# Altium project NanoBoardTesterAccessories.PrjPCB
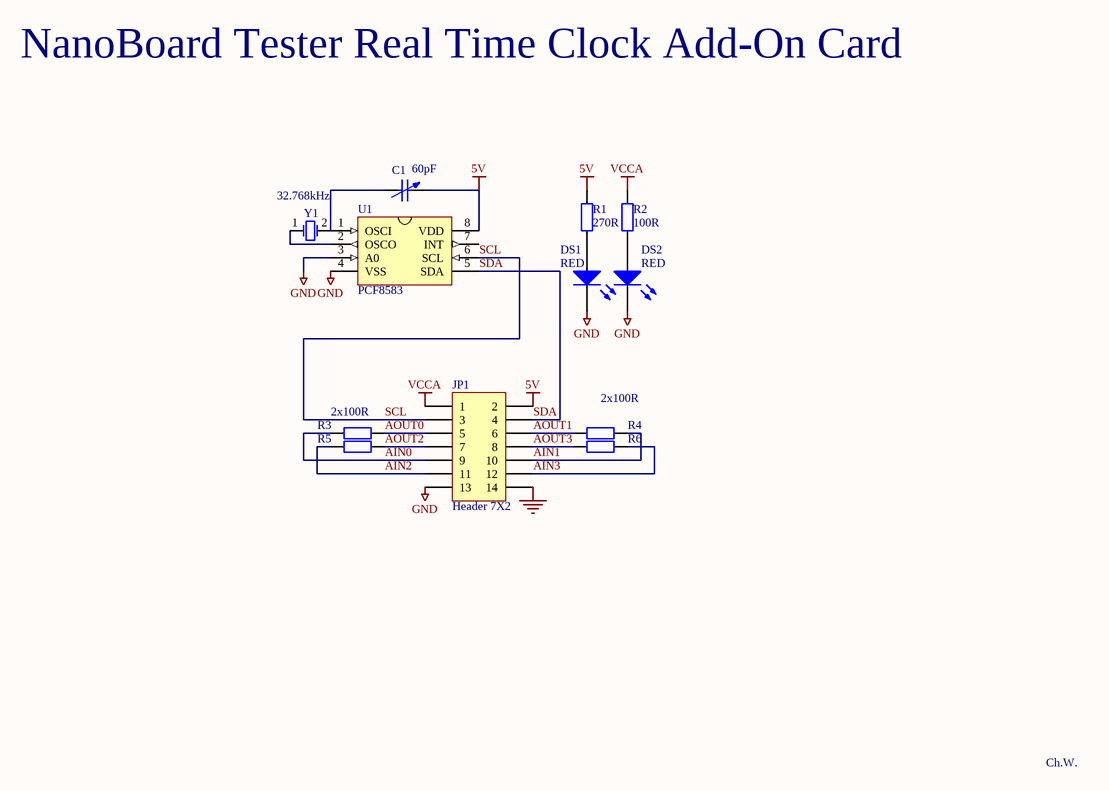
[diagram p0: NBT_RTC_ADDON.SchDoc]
3 sheets, 15 parts. Net scope: global (net labels, ports and power ports of the same name join across sheets).
Sheets:
  NBT_RTC_ADDON.SchDoc
  NBT_RS232_TESTPLUG.SchDoc
  NBT_JTAG_LOOP_CABLE.SCHDOC

## Sheet NBT_RTC_ADDON.SchDoc
size A4; Organization: Altium Limited; Address1: L3, 12a Rodborough Rd; Address2: Frenchs Forest; Address3: NSW; Address4: Australia 2086; DocumentNumber: 1; SheetNumber: 1; SheetTotal: 3

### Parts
C1  value 60pF  [C3225-1210]  (hidden comment: Cap Var)
DS1  LED2  [DSO-F2/D6.1]  (value not drawn)
DS2  LED2  [DSO-F2/D6.1]  (value not drawn)
JP1  Header 7X2  [HDR2X7]
R1  270R  [AXIAL-0.4]
R2  value 100R  [AXIAL-0.4]  (hidden comment: Generic Components)
R3  Res2  [AXIAL-0.4]  (value not drawn)
R4  Res2  [AXIAL-0.4]  (value not drawn)
R5  Res2  [AXIAL-0.4]  (value not drawn)
R6  Res2  [AXIAL-0.4]  (value not drawn)
U1  PCF8583  [DIP-8]
Y1  32.768kHz  [BCY-W2/D3.1]

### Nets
5V: C1.2 JP1.2 R1.2 U1.8(VDD)
GND: DS1.2(K) DS2.2(K) JP1.13 JP1.14 U1.3(A0) U1.4(VSS)
VCCA: JP1.1 R2.2
AIN0: JP1.9 R3.2
AIN1: JP1.10 R4.1
AIN2: JP1.11 R5.2
AIN3: JP1.12 R6.1
AOUT0: JP1.5 R3.1
AOUT1: JP1.6 R4.2
AOUT2: JP1.7 R5.1
AOUT3: JP1.8 R6.2
SCL: JP1.3 U1.6(SCL)
SDA: JP1.4 U1.5(SDA)
NetC1_1: C1.1 U1.1(OSCI) Y1.2(OSC2)
NetDS1_1: DS1.1(A) R1.1
NetDS2_1: DS2.1(A) R2.1
NetU1_2: U1.2(OSCO) Y1.1(OSC1)

Not connected (* = marked no-connect by the designer): U1 7(INT)

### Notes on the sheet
- NanoBoard Tester Real Time Clock Add-On Card
- (near R3) 2x100R
- 2x100R
- Ch.W.

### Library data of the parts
C1 = Cap Var: Variable or Adjustable Capacitor; Manufacturer: Generic Components; Class I: Passive
DS1 DS2 = LED2: Typical RED, GREEN, YELLOW, AMBER GaAs LED; Manufacturer: Generic Components; Class I: Optoelectronic
JP1 = Header 7X2: Header, 7-Pin, Dual row; Manufacturer: Generic Components; Class I: Connector
R1 = Res2: Resistor; Manufacturer: Generic Components; Class I: Passive
R2 = Res2: Resistor; Class I: Passive
R3-R6 = Res2: Resistor; Manufacturer: Generic Components; Class I: Passive; Value: 100R
U1 = PCF8583: Clock/Calendar with 240 x 8-bit RAM
Y1 = XTAL: Crystal Oscillator; Manufacturer: Generic Components

## Sheet NBT_RS232_TESTPLUG.SchDoc
size A4; Organization: Altium Limited; Address1: L3, 12a Rodborough Rd; Address2: Frenchs Forest; Address3: NSW; Address4: Australia 2086; DocumentNumber: 2; SheetNumber: 2; SheetTotal: 3
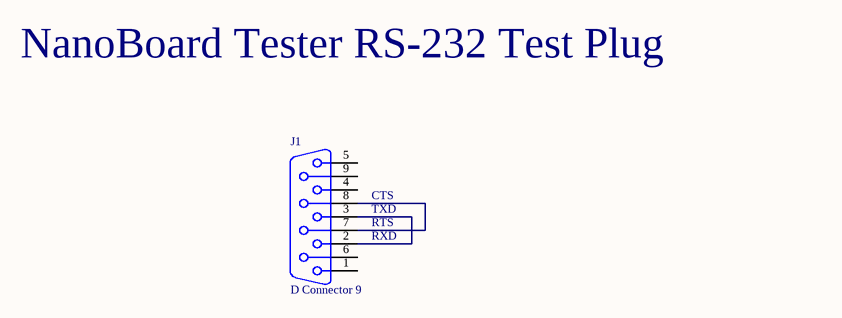
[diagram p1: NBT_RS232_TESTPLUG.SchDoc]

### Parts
J1  D Connector 9  [DSUB1.385-2H9]

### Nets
NetJ1_2: J1.2 J1.3
NetJ1_7: J1.7 J1.8

Not connected (* = marked no-connect by the designer): J1 1 4 5 6 9 10(MH1) 11(MH2)

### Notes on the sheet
- NanoBoard Tester RS-232 Test Plug
- (near J1) TXD
- (near J1) CTS
- (near J1) RXD
- (near J1) RTS

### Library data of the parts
J1 = D Connector 9: Receptacle Assembly, 9 Position, Right Angle; Manufacturer: Generic Components; Package Information: Latest Revision: O; Positions: 9

## Sheet NBT_JTAG_LOOP_CABLE.SCHDOC
size A4; Organization: Altium Limited; Address1: L3, 12a Rodborough Rd; Address2: Frenchs Forest; Address3: NSW; Address4: Australia 2086; DocumentNumber: 3; SheetNumber: 3; SheetTotal: 3
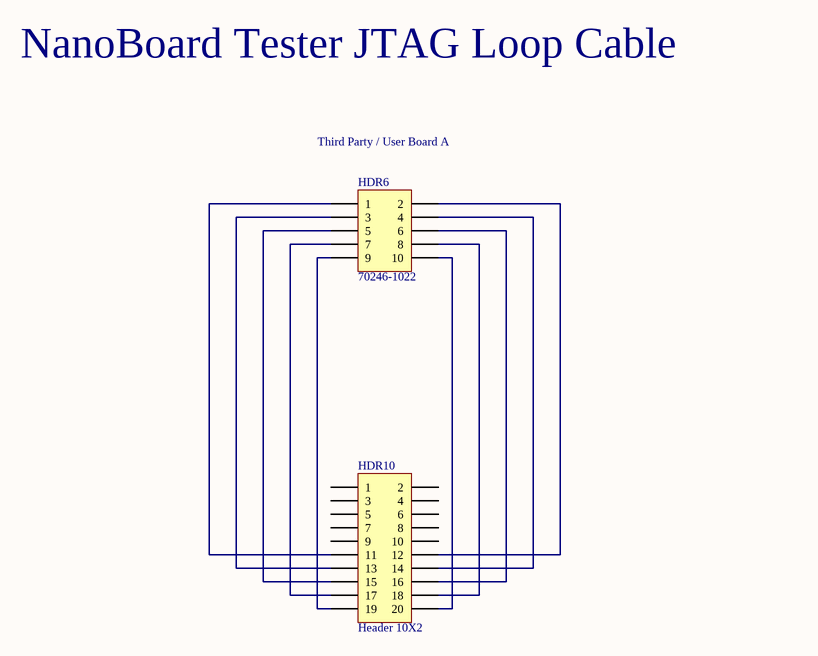
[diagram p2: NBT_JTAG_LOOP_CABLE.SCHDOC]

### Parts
HDR6  70246-1022  Usage: Third Party / User Board A  [HDR2X5_LP]
HDR10  Header 10X2  [HDR2X10]

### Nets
NetHDR6_1: HDR6.1 HDR10.11
NetHDR6_2: HDR6.2 HDR10.12
NetHDR6_3: HDR6.3 HDR10.13
NetHDR6_4: HDR6.4 HDR10.14
NetHDR6_5: HDR6.5 HDR10.15
NetHDR6_6: HDR6.6 HDR10.16
NetHDR6_7: HDR6.7 HDR10.17
NetHDR6_8: HDR6.8 HDR10.18
NetHDR6_9: HDR6.9 HDR10.19
NetHDR6_10: HDR6.10 HDR10.20

Not connected (* = marked no-connect by the designer): HDR10 1 2 3 4 5 6 7 8 9 10

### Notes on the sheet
- NanoBoard Tester JTAG Loop Cable

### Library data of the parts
HDR6 = Header 5X2: Header, 5-Pin, Dual row; Manufacturer: Molex; Class I: Connector; Fitted: True
HDR10 = Header 10X2: Header, 10-Pin, Dual row; Manufacturer: Generic Components; Class I: Connector; Fitted: True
